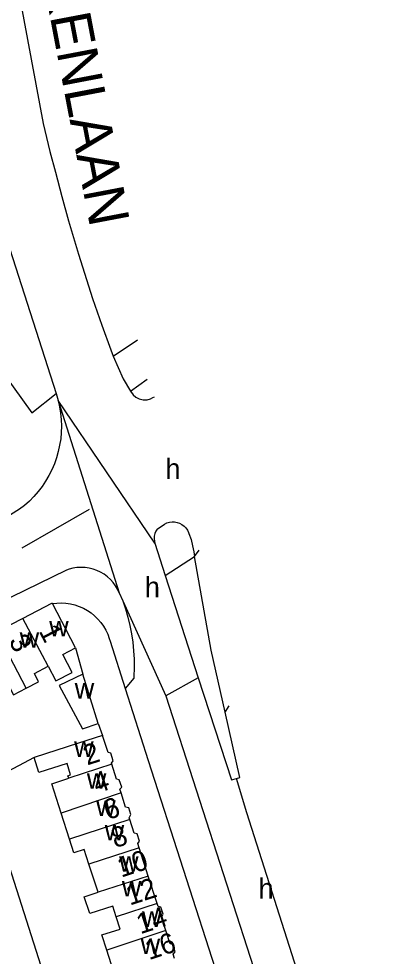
# Model space of a CAD drawing. Extents: x 157569 to 159501, y 382907 to 384670.
# Drawn here: x 159350.4 to 159425.1, y 383302.6 to 383488.1 of the extents above; entities that cross this region are included whole.
import ezdxf

# ---------------------------------------------------------------- set-up
doc = ezdxf.new("R2010")
doc.units = 0
for name, color, linetype in [('BLT_Basislijn', 7, 'Continuous'), ('BLT_Bebouwing', 7, 'Continuous'), ('BLT_Centroide', 7, 'Continuous'), ('BLT_Huisnummer', 7, 'Continuous'), ('BLT_Huisnummer_ tussenligend', 7, 'Continuous'), ('BLT_Onderverdeling_panden', 7, 'Continuous'), ('BLT_Straatnaam_hoofdweg', 7, 'Continuous'), ('BLT_Vlakafsluiter', 7, 'Continuous')]:
    doc.layers.add(name, color=color, linetype=linetype)

msp = doc.modelspace()

# ---------------------------------------------------------------- linework, layer by layer
at = {"layer": 'BLT_Basislijn'}
for p, q in [((159369.1, 383421.34), (159373.95, 383424.61)), ((159372.56, 383414.44), (159375.87, 383416.78)), ((159357.85, 383413.94), (159358.25, 383412.58)), ((159350.59, 383391.04), (159328.07, 383377.48)), ((159351.08, 383383.39), (159364.41, 383391.04)), ((159377.81, 383387.13), (159379.3, 383388.11)), ((159377.38, 383384.36), (159379.39, 383377.91)), ((159379.39, 383377.91), (159385.22, 383381.68)), ((159359.86, 383378.99), (159336.5, 383367.59)), ((159379.39, 383377.91), (159385.97, 383357.69)), ((159370.33, 383374.48), (159371.03, 383372.94)), ((159368.51, 383364.97), (159371.51, 383355.59)), ((159361.64, 383363.6), (159363.12, 383358.39)), ((159373.18, 383357.61), (159371.51, 383355.59)), ((159385.97, 383357.69), (159392.54, 383337.47)), ((159371.51, 383355.59), (159376.06, 383341.3)), ((159379.54, 383354.13), (159408.56, 383264.22)), ((159366.17, 383348.65), (159367.01, 383346.29)), ((159376.06, 383341.3), (159400.22, 383266.41)), ((159392.54, 383337.47), (159393.53, 383337.77)), ((159393.53, 383337.77), (159394.2, 383337.97)), ((159395.57, 383330.94), (159393.53, 383337.77)), ((159425.15, 383238.36), (159395.57, 383330.94))]:
    msp.add_line(p, q, dxfattribs=at)
for points in [[(159347.43, 383509.38), (159347.63, 383508.48), (159355.25, 383467.4), (159356.59, 383461.84), (159357.69, 383457.75), (159358.96, 383452.98), (159360.3, 383448.11), (159362.29, 383441.51), (159365.03, 383432.79), (159366.89, 383427.51), (159368.68, 383422.6), (159369.1, 383421.34)], [(159335.28, 383507.65), (159335.95, 383504.21), (159336.46, 383501.41), (159336.6, 383498.86), (159336.48, 383488.16), (159336.47, 383487.23), (159336.52, 383485.67), (159336.7, 383484.25), (159336.87, 383483.11), (159337.15, 383482.06), (159338.1, 383478.01), (159342.79, 383461.1), (159348.66, 383442.54), (159357.85, 383413.94)], [(159319.38, 383456.9), (159353.02, 383410.14), (159357.85, 383413.94)], [(159369.1, 383421.34), (159371.07, 383416.87), (159372.56, 383414.44)], [(159372.56, 383414.44), (159373.06, 383413.71), (159373.63, 383413.22), (159374.28, 383412.89), (159375.06, 383412.7), (159375.84, 383412.73), (159376.48, 383412.89), (159376.98, 383413.14), (159377.28, 383413.32)], [(159358.25, 383412.58), (159358.51, 383411.32), (159358.71, 383410.06), (159358.84, 383408.79), (159358.88, 383407.52), (159358.84, 383406.24), (159358.73, 383404.97), (159358.53, 383403.71), (159358.26, 383402.46), (159357.91, 383401.23), (159357.48, 383400.03), (159356.98, 383398.86), (159356.4, 383397.72), (159355.76, 383396.61), (159355.05, 383395.55), (159354.27, 383394.54), (159353.43, 383393.58), (159352.53, 383392.67), (159351.58, 383391.82), (159350.59, 383391.04)], [(159379.3, 383388.11), (159379.77, 383388.33), (159380.26, 383388.48), (159380.77, 383388.55), (159381.29, 383388.54), (159381.8, 383388.45), (159382.28, 383388.28), (159382.74, 383388.04), (159383.15, 383387.73), (159383.51, 383387.36), (159383.81, 383386.94), (159384.04, 383386.48), (159384.13, 383386.23)], [(159377.81, 383387.13), (159377.55, 383386.7), (159377.37, 383386.24), (159377.26, 383385.75), (159377.23, 383385.26), (159377.28, 383384.76), (159377.38, 383384.36)], [(159384.13, 383386.23), (159384.53, 383385.04), (159384.85, 383383.82), (159385.09, 383382.59), (159385.22, 383381.68)], [(159391.29, 383350.87), (159388.52, 383363.18), (159385.22, 383381.68)], [(159370.33, 383374.48), (159369.99, 383375.21), (159369.58, 383375.9), (159369.11, 383376.55), (159368.57, 383377.15), (159367.97, 383377.69), (159367.33, 383378.18), (159366.64, 383378.59), (159365.91, 383378.93), (159365.15, 383379.2), (159364.37, 383379.4), (159363.57, 383379.51), (159362.77, 383379.55), (159361.96, 383379.51), (159361.17, 383379.38), (159360.39, 383379.18), (159359.86, 383378.99)], [(159357.09, 383372.37), (159357.98, 383372.47), (159358.88, 383372.5), (159359.78, 383372.45), (159360.67, 383372.31), (159361.54, 383372.1), (159362.4, 383371.82), (159363.22, 383371.45), (159364.01, 383371.02), (159364.75, 383370.52), (159365.45, 383369.95), (159366.09, 383369.32), (159366.68, 383368.64), (159367.21, 383367.91), (159367.66, 383367.14), (159368.05, 383366.32), (159368.36, 383365.48), (159368.51, 383364.97)], [(159371.03, 383372.94), (159371.53, 383371.32), (159372.01, 383369.7), (159372.42, 383368.05), (159372.75, 383366.4), (159373, 383364.72), (159373.17, 383363.04), (159373.26, 383361.35), (159373.27, 383359.66), (159373.21, 383357.97), (159373.18, 383357.61)], [(159394.2, 383337.97), (159391.29, 383350.87)], [(159353.47, 383341.91), (159343.11, 383336.45)]]:
    msp.add_lwpolyline(points, dxfattribs=at)
at = {"layer": 'BLT_Bebouwing'}
for p, q in [((159361.64, 383363.6), (159357.09, 383372.37)), ((159351.25, 383369.45), (159346.07, 383366.76)), ((159363.12, 383358.39), (159358.45, 383356.18)), ((159366.17, 383348.65), (159363.12, 383358.39)), ((159358.45, 383356.18), (159363.07, 383347.59)), ((159363.07, 383347.59), (159366.17, 383348.65)), ((159360.49, 383325.77), (159358.83, 383330.89)), ((159346.57, 383326.35), (159354.8, 383300.68)), ((159376.06, 383318.45), (159374.26, 383324.01)), ((159366.12, 383315.24), (159364.32, 383320.79)), ((159377.83, 383312.98), (159376.06, 383318.45))]:
    msp.add_line(p, q, dxfattribs=at)
for points in [[(159357.09, 383372.37), (159356.9, 383372.38), (159351.25, 383369.45)], [(159356.25, 383359.97), (159357.76, 383357.06), (159361.02, 383358.75), (159359.17, 383362.32), (159361.64, 383363.6)], [(159351.93, 383355.64), (159354.37, 383356.9), (159353.54, 383358.52), (159356.25, 383359.97)], [(159344.9, 383356.55), (159347.55, 383357.92), (159349.41, 383354.33), (159351.93, 383355.64)], [(159367.01, 383346.29), (159362.25, 383344.75), (159353.47, 383341.91)], [(159368.85, 383340.56), (159368.78, 383340.77), (159369.15, 383341.28), (159368.66, 383342.79), (159368.1, 383342.9), (159367.01, 383346.29)], [(159360.32, 383337.79), (159360.16, 383338.3), (159360.7, 383338.47), (159360.03, 383340.72), (159354.44, 383338.91), (159353.47, 383341.91)], [(159370.68, 383334.93), (159370.45, 383335.62), (159370.81, 383336.01), (159370.32, 383337.52), (159369.8, 383337.63), (159368.85, 383340.56)], [(159358.83, 383330.89), (159356.95, 383336.7), (159360.32, 383337.79)], [(159372.41, 383329.63), (159372.3, 383329.98), (159372.63, 383330.62), (159372.19, 383331.98), (159371.59, 383332.11), (159370.68, 383334.93)], [(159374.26, 383324.01), (159373.97, 383324.9), (159374.36, 383325.33), (159373.89, 383326.79), (159373.29, 383326.92), (159372.41, 383329.63)], [(159364.32, 383320.79), (159363.36, 383323.72), (159361.36, 383323.07), (159360.49, 383325.77)], [(159369.74, 383310.35), (159369.04, 383312.49), (159364.49, 383311.02), (159363.41, 383314.36), (159366.12, 383315.24)], [(159379.54, 383307.67), (159378.7, 383310.26), (159379.03, 383310.91), (159378.58, 383312.32), (159378.01, 383312.44), (159377.83, 383312.98)], [(159367.86, 383303.77), (159366.89, 383306.78), (159370.51, 383307.96), (159369.74, 383310.35)], [(159381.29, 383302.14), (159381.02, 383303.01), (159381.41, 383303.45), (159380.94, 383304.93), (159380.39, 383305.04), (159379.54, 383307.67)], [(159369.57, 383298.35), (159367.86, 383303.77)]]:
    msp.add_lwpolyline(points, dxfattribs=at)
at = {"layer": 'BLT_Onderverdeling_panden'}
for p, q in [((159351.93, 383355.64), (159346.07, 383366.76)), ((159368.85, 383340.56), (159360.32, 383337.79)), ((159370.68, 383334.93), (159358.83, 383330.89)), ((159372.41, 383329.63), (159360.49, 383325.77)), ((159374.26, 383324.01), (159364.32, 383320.79)), ((159376.06, 383318.45), (159366.12, 383315.24)), ((159377.83, 383312.98), (159369.74, 383310.35)), ((159379.54, 383307.67), (159367.86, 383303.77))]:
    msp.add_line(p, q, dxfattribs=at)
msp.add_lwpolyline([(159356.25, 383359.97), (159355.15, 383362.08), (159351.25, 383369.45)], dxfattribs=at)
at = {"layer": 'BLT_Vlakafsluiter'}
for p, q in [((159377.38, 383384.36), (159358.25, 383412.58)), ((159358.25, 383412.58), (159370.33, 383374.48)), ((159385.22, 383381.68), (159386.12, 383382.98)), ((159371.03, 383372.94), (159379.54, 383354.13)), ((159385.97, 383357.69), (159379.54, 383354.13)), ((159391.29, 383350.87), (159392.09, 383352.13))]:
    msp.add_line(p, q, dxfattribs=at)

# ---------------------------------------------------------------- texts
at = {"layer": 'BLT_Centroide'}
for s, p in [('h', (159379.46, 383397.07)), ('h', (159375.4, 383373.64)), ('w', (159356.45, 383365.88)), ('w', (159350.61, 383363.64)), ('w', (159361.51, 383353.58)), ('w', (159361.39, 383342.03)), ('w', (159363.91, 383335.72)), ('w', (159365.75, 383330.34)), ('w', (159367.45, 383325.5)), ('w', (159370.29, 383319.31)), ('w', (159370.84, 383314.41)), ('h', (159397.9, 383313.99)), ('w', (159374.84, 383308.38)), ('w', (159374.56, 383303))]:
    msp.add_text(s, height=4, dxfattribs=at).set_placement(p)
at = {"layer": 'BLT_Huisnummer'}
for s, rotation, p in [('1', 297.8423, (159354.32, 383366.95)), ('2', 17.9431, (159363.97, 383340.32)), ('6', 17.9399, (159367.99, 383329.49)), ('10', 17.9399, (159370.7, 383318.12)), ('14', 17.9296, (159374.5, 383306.91))]:
    msp.add_text(s, height=4, rotation=rotation, dxfattribs=at).set_placement(p)
at = {"layer": 'BLT_Huisnummer_ tussenligend'}
for s, rotation, p in [('3', 297.8423, (159348.36, 383365)), ('4', 17.9431, (159365.87, 383334.77)), ('8', 17.9399, (159369.49, 383323.95)), ('12', 17.9399, (159372.41, 383312.59)), ('16', 17.9296, (159376.21, 383301.79))]:
    msp.add_text(s, height=4, rotation=rotation, dxfattribs=at).set_placement(p)
at = {"layer": 'BLT_Straatnaam_hoofdweg'}
msp.add_text('BEUKENLAAN', height=8, rotation=280.7873, dxfattribs=at).set_placement((159351.12, 383517.29))

doc.saveas('drawing.dxf')
